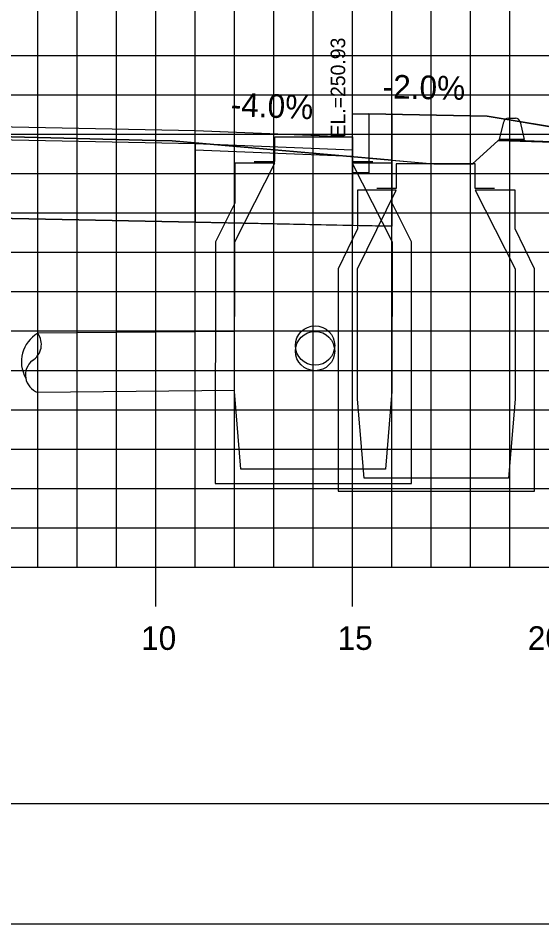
# Model space of a CAD drawing. Extents: x 859352 to 859522, y 366268 to 366378.
# Drawn here: x 859441.63 to 859454.94, y 366268.18 to 366291.18 of the extents above; entities that cross this region are included whole.
import ezdxf

# ---------------------------------------------------------------- set-up
doc = ezdxf.new("R2010")
doc.units = 0
for name, color, linetype in [('ANNOTATION', 7, 'Continuous'), ('BORDER', 7, 'Continuous'), ('D_Curb_Type_1_Rt', 7, 'Continuous'), ('D_Drainage_CB_TypeA1-B1', 7, 'Continuous'), ('D_Roadway_Centerline', 7, 'Continuous'), ('D_Roadway_Edge_Shoulder', 7, 'Continuous'), ('D_Roadway_FinishedGrade', 7, 'Continuous'), ('D_Roadway_SubGrade', 7, 'Continuous'), ('D_Text_Standard', 7, 'Continuous'), ('H_V ANNOTATION', 7, 'Continuous'), ('JUNK COM EXC', 7, 'Continuous'), ('JUNK FILL', 7, 'Continuous'), ('MAJOR', 7, 'Continuous'), ('MINOR', 7, 'Continuous'), ('PDRAIN', 7, 'Continuous'), ('PLOT BOUNDARY', 7, 'Continuous'), ('S_Curb_Type_3', 7, 'Continuous'), ('S_Drainage_CB', 7, 'Continuous'), ('S_Roadway_Centerline', 7, 'Continuous')]:
    doc.layers.add(name, color=color, linetype=linetype)

msp = doc.modelspace()

# ---------------------------------------------------------------- linework, layer by layer
at = {"layer": 'BORDER'}
msp.add_line((859360.13, 366271.236), (859520.13, 366271.236), dxfattribs=at)
at = {"layer": 'D_Curb_Type_1_Rt'}
msp.add_lwpolyline([(859450.546, 366288.752), (859450.546, 366287.252), (859450.129, 366287.252), (859450.129, 366288.752)], close=True, dxfattribs=at)
at = {"layer": 'D_Drainage_CB_TypeA1-B1'}
for p, q in [((859447.135, 366287.501), (859447.135, 366286.484)), ((859447.135, 366285.5), (859448.153, 366287.501)), ((859448.153, 366287.501), (859447.135, 366287.501)), ((859451.138, 366287.501), (859450.121, 366287.501)), ((859450.121, 366287.501), (859451.138, 366285.5)), ((859451.138, 366286.484), (859451.138, 366287.501)), ((859447.135, 366286.484), (859446.643, 366285.5)), ((859451.63, 366285.5), (859451.138, 366286.484)), ((859446.643, 366285.5), (859446.636, 366279.366)), ((859447.128, 366281.695), (859447.135, 366285.5)), ((859451.138, 366285.5), (859451.131, 366281.695)), ((859451.623, 366279.366), (859451.63, 366285.5)), ((859447.292, 366279.726), (859447.128, 366281.695)), ((859451.131, 366281.695), (859450.967, 366279.726)), ((859450.967, 366279.726), (859447.292, 366279.726)), ((859446.636, 366279.366), (859451.623, 366279.366))]:
    msp.add_line(p, q, dxfattribs=at)
msp.add_lwpolyline([(859447.628, 366287.543), (859448.153, 366287.543), (859448.153, 366288.166), (859450.121, 366288.166), (859450.121, 366287.543), (859450.646, 366287.543)], dxfattribs=at)
at = {"layer": 'D_Roadway_Centerline'}
msp.add_lwpolyline([(859424.129, 366288.328), (859435.129, 366288.548), (859446.129, 366288.328)], dxfattribs=at)
at = {"layer": 'D_Roadway_Edge_Shoulder'}
msp.add_lwpolyline([(859420.129, 366288.168), (859424.129, 366288.328), (859435.129, 366288.548), (859446.129, 366288.328), (859450.121, 366288.169)], dxfattribs=at)
msp.add_lwpolyline([(859446.129, 366288.328), (859450.129, 366288.168), (859450.129, 366287.668), (859446.129, 366287.828)], close=True, dxfattribs=at)
at = {"layer": 'D_Roadway_FinishedGrade'}
msp.add_line((859453.546, 366288.691), (859458.093, 366287.934), dxfattribs=at)
msp.add_lwpolyline([(859450.546, 366288.751), (859453.546, 366288.691)], dxfattribs=at)
at = {"layer": 'D_Roadway_SubGrade'}
msp.add_lwpolyline([(859451.129, 366288.763), (859451.129, 366285.895), (859450.129, 366285.915)], dxfattribs=at)
for points in [[(859424.129, 366285.995), (859424.129, 366287.995), (859435.129, 366288.215), (859446.129, 366287.995), (859446.129, 366285.995), (859435.129, 366286.215)], [(859446.129, 366287.995), (859450.129, 366287.835), (859450.129, 366285.915), (859446.129, 366285.995)]]:
    msp.add_lwpolyline(points, close=True, dxfattribs=at)
at = {"layer": 'JUNK COM EXC'}
msp.add_lwpolyline([(859415.124, 366288.509), (859415.124, 366287.676), (859419.129, 366287.596), (859419.129, 366285.895), (859424.129, 366285.995), (859435.129, 366286.215), (859446.129, 366285.995), (859451.129, 366285.895), (859451.129, 366287.577), (859445.548, 366288.061), (859445.111, 366288.071), (859435.808, 366288.308), (859426.117, 366288.123), (859424.997, 366288.101), (859424.392, 366288.075), (859422.855, 366287.987), (859420.57, 366287.867), (859420.271, 366287.854), (859419.808, 366288.366), (859419.782, 366288.389), (859419.446, 366288.403), (859418.024, 366288.437), (859415.124, 366288.509)], dxfattribs=at)
at = {"layer": 'JUNK FILL'}
msp.add_lwpolyline([(859450.546, 366287.627), (859451.129, 366287.577), (859452.194, 366287.484), (859453.169, 366287.475), (859453.829, 366288.077), (859455.515, 366288.025), (859458.093, 366287.934), (859453.546, 366288.691), (859450.546, 366288.751)], close=True, dxfattribs=at)
at = {"layer": 'MAJOR'}
for p, q in [((859445.129, 366277.236), (859445.129, 366297.236)), ((859450.129, 366277.236), (859450.129, 366297.236)), ((859365.129, 366287.236), (859505.129, 366287.236)), ((859365.129, 366282.236), (859505.129, 366282.236)), ((859365.129, 366277.236), (859505.129, 366277.236)), ((859365.129, 366277.236), (859505.129, 366277.236)), ((859445.129, 366276.234), (859445.129, 366277.236)), ((859450.129, 366276.234), (859450.129, 366277.236))]:
    msp.add_line(p, q, dxfattribs=at)
at = {"layer": 'MINOR'}
for p, q in [((859442.129, 366277.236), (859442.129, 366297.236)), ((859443.129, 366277.236), (859443.129, 366297.236)), ((859444.129, 366277.236), (859444.129, 366297.236)), ((859446.129, 366277.236), (859446.129, 366297.236)), ((859447.129, 366277.236), (859447.129, 366297.236)), ((859448.129, 366277.236), (859448.129, 366297.236)), ((859449.129, 366277.236), (859449.129, 366297.236)), ((859451.129, 366277.236), (859451.129, 366297.236)), ((859452.129, 366277.236), (859452.129, 366297.236)), ((859453.129, 366277.236), (859453.129, 366297.236)), ((859454.129, 366277.236), (859454.129, 366297.236)), ((859365.129, 366290.236), (859505.129, 366290.236)), ((859365.129, 366289.236), (859505.129, 366289.236)), ((859365.129, 366288.236), (859505.129, 366288.236)), ((859365.129, 366286.236), (859505.129, 366286.236)), ((859365.129, 366285.236), (859505.129, 366285.236)), ((859365.129, 366284.236), (859505.129, 366284.236)), ((859365.129, 366283.236), (859505.129, 366283.236)), ((859365.129, 366281.236), (859505.129, 366281.236)), ((859365.129, 366280.236), (859505.129, 366280.236)), ((859365.129, 366279.236), (859505.129, 366279.236)), ((859365.129, 366278.236), (859505.129, 366278.236))]:
    msp.add_line(p, q, dxfattribs=at)
at = {"layer": 'PDRAIN'}
for p, q in [((859447.114, 366283.226), (859442.114, 366283.176)), ((859447.129, 366281.726), (859442.129, 366281.676))]:
    msp.add_line(p, q, dxfattribs=at)
for centre in [(859449.175, 366282.866), (859449.175, 366282.726)]:
    msp.add_circle(centre, 0.5, dxfattribs=at)
for centre, radius, start, end in [((859442.55, 366282.453), 0.837, 120.1627, 209.5006), ((859441.74, 366282.895), 0.48, 301.6297, 35.9187), ((859442.283, 366282.119), 0.468, 128.3832, 250.8558)]:
    msp.add_arc(centre, radius, start, end, dxfattribs=at)
at = {"layer": 'PLOT BOUNDARY'}
msp.add_lwpolyline([(859352.036, 366268.177), (859522.036, 366268.177), (859522.036, 366378.177), (859352.036, 366378.177)], close=True, dxfattribs=at)
at = {"layer": 'S_Curb_Type_3'}
for points in [[(859454.389, 366288.545), (859454.492, 366288.1), (859453.867, 366288.1), (859453.969, 366288.545)], [(859454.091, 366288.642), (859454.267, 366288.642)]]:
    msp.add_lwpolyline(points, dxfattribs=at)
for centre, start, end in [((859454.091, 366288.517), 90, 167.0054), ((859454.267, 366288.517), 12.9946, 90)]:
    msp.add_arc(centre, 0.125, start, end, dxfattribs=at)
at = {"layer": 'S_Drainage_CB'}
for p, q in [((859451.241, 366286.815), (859450.257, 366286.815)), ((859450.257, 366286.815), (859450.257, 366285.83)), ((859450.257, 366284.813), (859451.241, 366286.815)), ((859454.259, 366286.815), (859453.242, 366286.815)), ((859453.242, 366286.815), (859454.259, 366284.813)), ((859454.259, 366285.83), (859454.259, 366286.815)), ((859450.257, 366285.83), (859449.765, 366284.813)), ((859454.752, 366284.813), (859454.259, 366285.83)), ((859449.765, 366284.813), (859449.765, 366279.17)), ((859450.257, 366281.5), (859450.257, 366284.813)), ((859454.259, 366284.813), (859454.259, 366281.5)), ((859454.752, 366279.17), (859454.752, 366284.813)), ((859450.421, 366279.498), (859450.257, 366281.5)), ((859454.259, 366281.5), (859454.095, 366279.498)), ((859454.095, 366279.498), (859450.421, 366279.498)), ((859449.765, 366279.17), (859454.752, 366279.17))]:
    msp.add_line(p, q, dxfattribs=at)
msp.add_lwpolyline([(859453.735, 366286.856), (859453.242, 366286.856), (859453.242, 366287.48), (859451.241, 366287.48), (859451.241, 366286.856), (859450.749, 366286.856)], dxfattribs=at)
at = {"layer": 'S_Roadway_Centerline'}
msp.add_lwpolyline([(859406.448, 366287.989), (859414.498, 366288.475), (859414.863, 366288.516), (859418.024, 366288.437), (859419.446, 366288.403), (859419.782, 366288.389), (859419.808, 366288.366), (859420.271, 366287.854), (859420.57, 366287.867), (859422.855, 366287.987), (859424.392, 366288.075), (859424.997, 366288.101), (859426.117, 366288.123), (859435.808, 366288.308), (859445.111, 366288.071), (859445.548, 366288.061), (859452.194, 366287.484), (859452.255, 366287.481), (859453.169, 366287.475), (859453.829, 366288.077), (859453.867, 366288.1), (859456.735, 366287.987), (859463.938, 366287.704), (859477.165, 366287.052)], dxfattribs=at)

# ---------------------------------------------------------------- texts
at = {"layer": 'ANNOTATION'}
for s, rotation, p in [('-2.0%', 358.8543, (859450.889, 366289.145)), ('-4.0%', 357.7096, (859447.024, 366288.694))]:
    msp.add_text(s, height=0.6, rotation=rotation, dxfattribs=at).set_placement(p)
at = {"layer": 'D_Text_Standard'}
msp.add_text(' EL.=250.93', height=0.36848, rotation=90, dxfattribs=at).set_placement((859449.941, 366288.014))
at = {"layer": 'H_V ANNOTATION'}
for s, p in [('10', (859444.755, 366275.136)), ('15', (859449.747, 366275.136)), ('20', (859454.583, 366275.136))]:
    msp.add_text(s, height=0.6, dxfattribs=at).set_placement(p)

doc.saveas('drawing.dxf')
